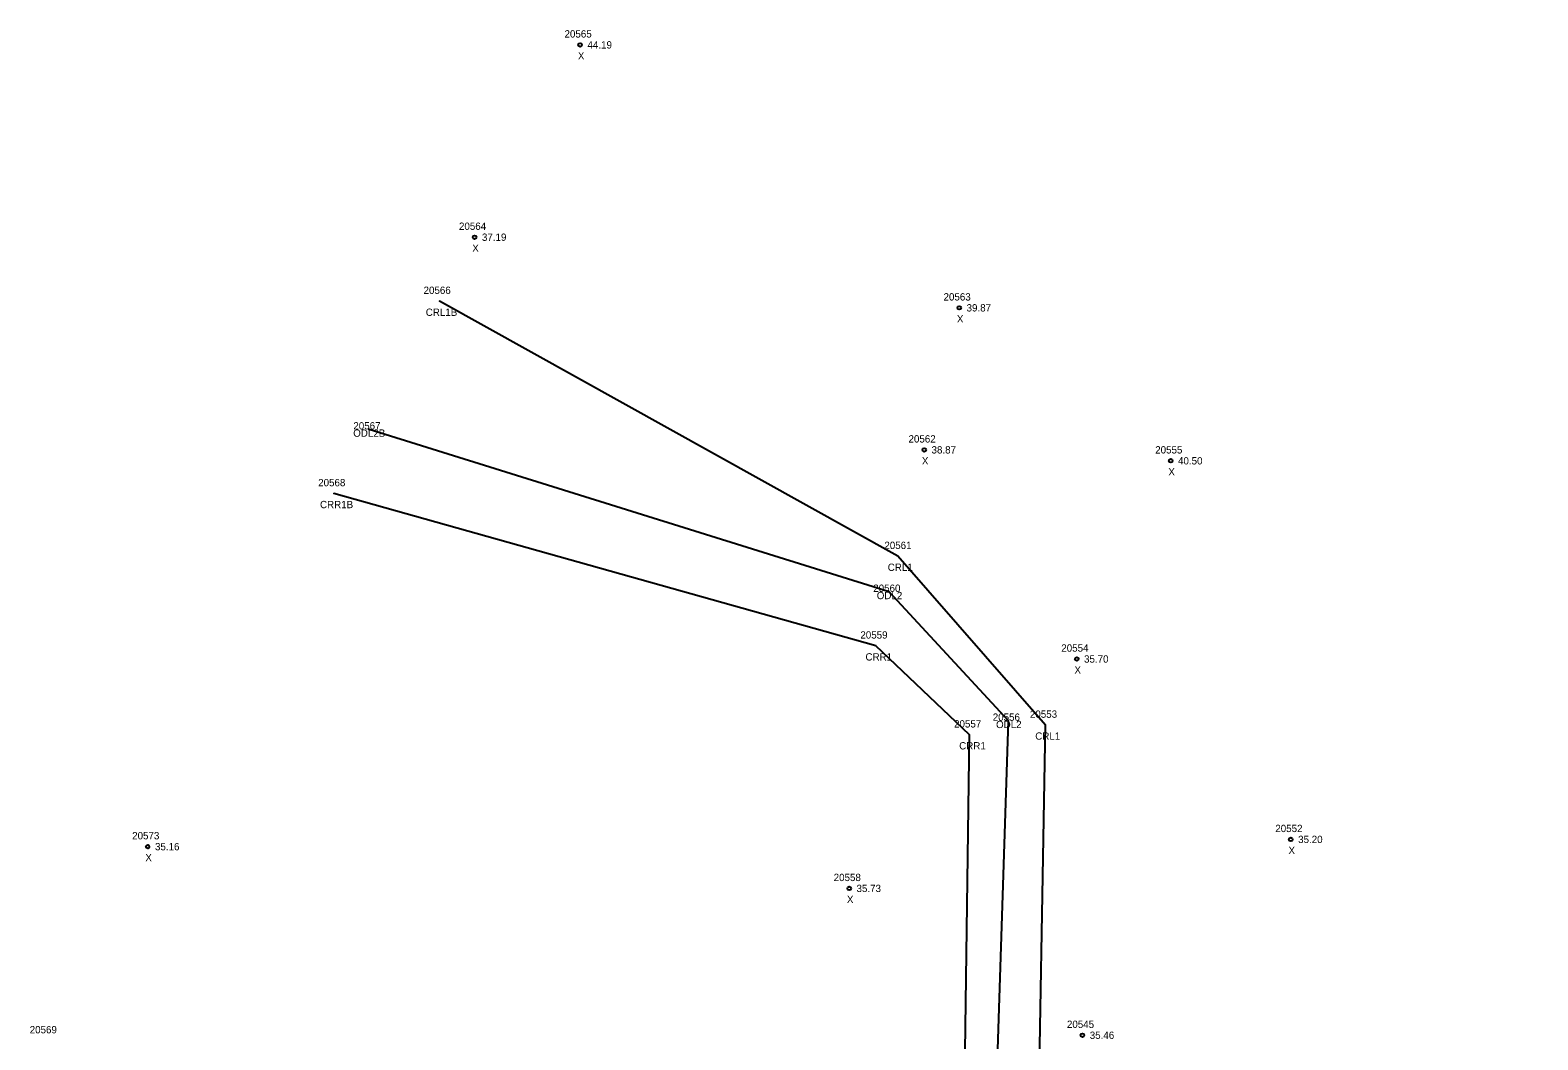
# Model space of a CAD drawing. Extents: x 2445178 to 2446260, y 791158 to 792318.
# Drawn here: x 2445209.1 to 2445415.2, y 792087.9 to 792226 of the extents above; entities that cross this region are included whole.
import ezdxf

# ---------------------------------------------------------------- set-up
doc = ezdxf.new("R2010")
doc.units = 0
for name, color, linetype in [('RD_EX_H2O', 7, 'Continuous'), ('RD_EX_H2O_txCode', 7, 'Continuous'), ('RD_Sketch8', 7, 'Continuous'), ('RD_SMD_Locator', 7, 'Continuous'), ('RD_SMD_Misc', 7, 'Continuous')]:
    doc.layers.add(name, color=color, linetype=linetype)

msp = doc.modelspace()

# ---------------------------------------------------------------- linework, layer by layer
at = {"layer": 'RD_EX_H2O'}
for points in [[(2445415.21, 791826.15), (2445411.13, 791915.36), (2445401.26, 791978.48), (2445346.75, 792066.4), (2445347.89, 792130.96), (2445327.72, 792154.04), (2445265.04, 792188.92)], [(2445409.65, 791824.04), (2445406.98, 791914.3), (2445391.36, 791973.89), (2445340.62, 792062.76), (2445342.84, 792131.55), (2445326.53, 792149.18), (2445255.41, 792171.39)], [(2445403.09, 791820.76), (2445401.57, 791912.69), (2445385.3, 791968.86), (2445336.54, 792059.75), (2445337.52, 792129.63), (2445324.7, 792141.79), (2445250.6, 792162.62)]]:
    msp.add_lwpolyline(points, dxfattribs=at)
at = {"layer": 'RD_SMD_Locator'}
for centre, radius in [((2445284.28, 792223.98), 0.25), ((2445269.85, 792197.68), 0.25), ((2445265.04, 792188.92), 0.001), ((2445336.11, 792188.02), 0.25), ((2445255.41, 792171.39), 0.001), ((2445331.32, 792168.6), 0.25), ((2445365.02, 792167.1), 0.25), ((2445250.6, 792162.62), 0.001), ((2445327.72, 792154.04), 0.001), ((2445326.53, 792149.18), 0.001), ((2445324.7, 792141.79), 0.001), ((2445352.17, 792140), 0.25), ((2445342.84, 792131.55), 0.001), ((2445347.89, 792130.96), 0.001), ((2445337.52, 792129.63), 0.001), ((2445225.15, 792114.34), 0.25), ((2445381.44, 792115.33), 0.25), ((2445321.06, 792108.63), 0.25), ((2445352.95, 792088.55), 0.25)]:
    msp.add_circle(centre, radius, dxfattribs=at)

# ---------------------------------------------------------------- texts
at = {"layer": 'RD_EX_H2O_txCode'}
for s, p in [('20566', (2445262.87, 792189.92)), ('CRL1B', (2445263.17, 792186.92)), ('ODL2B', (2445253.25, 792170.39)), ('20567', (2445253.27, 792171.39)), ('20568', (2445248.46, 792163.62)), ('CRR1B', (2445248.71, 792160.62)), ('20561', (2445325.87, 792155.04)), ('CRL1', (2445326.33, 792152.04)), ('20560', (2445324.35, 792149.18)), ('ODL2', (2445324.83, 792148.18)), ('20559', (2445322.59, 792142.79)), ('CRR1', (2445323.29, 792139.79)), ('20556', (2445340.69, 792131.55)), ('20553', (2445345.77, 792131.96)), ('20557', (2445335.4, 792130.63)), ('ODL2', (2445341.14, 792130.55)), ('CRR1', (2445336.1, 792127.63)), ('CRL1', (2445346.5, 792128.96))]:
    msp.add_text(s, height=1, dxfattribs=at).set_placement(p)
at = {"layer": 'RD_Sketch8'}
for s, p in [('20565', (2445282.14, 792224.98)), ('X', (2445283.97, 792221.98)), ('44.19', (2445285.28, 792223.48)), ('20564', (2445267.71, 792198.68)), ('37.19', (2445270.85, 792197.18)), ('X', (2445269.53, 792195.68)), ('20563', (2445333.96, 792189.02)), ('39.87', (2445337.11, 792187.52)), ('X', (2445335.79, 792186.02)), ('20562', (2445329.17, 792169.6)), ('X', (2445331, 792166.6)), ('38.87', (2445332.32, 792168.1)), ('20555', (2445362.9, 792168.1)), ('40.50', (2445366.02, 792166.6)), ('X', (2445364.7, 792165.1)), ('20554', (2445350.06, 792141)), ('35.70', (2445353.17, 792139.5)), ('X', (2445351.86, 792138)), ('20573', (2445223.03, 792115.34)), ('20552', (2445379.32, 792116.33)), ('35.20', (2445382.44, 792114.83)), ('35.16', (2445226.15, 792113.84)), ('X', (2445381.12, 792113.33)), ('X', (2445224.83, 792112.34)), ('20558', (2445318.94, 792109.63)), ('X', (2445320.75, 792106.63)), ('35.73', (2445322.06, 792108.13)), ('20545', (2445350.83, 792089.55)), ('35.46', (2445353.95, 792088.05))]:
    msp.add_text(s, height=1, dxfattribs=at).set_placement(p)
at = {"layer": 'RD_SMD_Misc'}
msp.add_text('20569', height=1, dxfattribs=at).set_placement((2445209.02, 792088.81))

doc.saveas('drawing.dxf')
